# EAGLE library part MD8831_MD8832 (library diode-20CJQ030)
M-System's DiskOnChip G4 128MB (1Gb)/256MB (2Gb) 1.8V Flash Disk with MLC NAND and M-Systems x2 Technology Description: DiskOnChip G4 is M-Systems' 4th generation of the DiskOnChip family of products. Based on Multi-Level Cell (MLC) NAND, utilizing Toshiba's 90nm MLC NAND Large Block flash technology and x2 technology from MSystems, it is one of the industry's most efficient storage solutions. MLC NAND flash technology provides the smallest die size by storing 2 bits of information in a single memory cell. x2 technology enables MLC NAND to achieve highly reliable, high-performance data and code storage with a specially designed error detection and correction mechanism, optimized file management, and proprietary algorithms for enhanced performance. Further cost benefits derive from the cost-effective architecture of DiskOnChip G4, which includes a boot block that can replace expensive NOR flash, and incorporates both the flash array and an embedded thin controller in a single die. Features: Flash disk for both code and data storage Low voltage: 1.8V core and I/O Hardware protection and security-enabling features High capacity: single die - 1Gb (128MB), dual die - 2Gb (256MB) Device cascade capacity: up to 4Gb (512MB) Enhanced Programmable Boot Block enabling eXecute In Place (XIP) functionality using 16-bit interface Small form factors: 69-ball FBGA 9x12 mm package Enhanced performance by implementation of: DMA support MultiBurst operation Unrivaled data integrity with a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
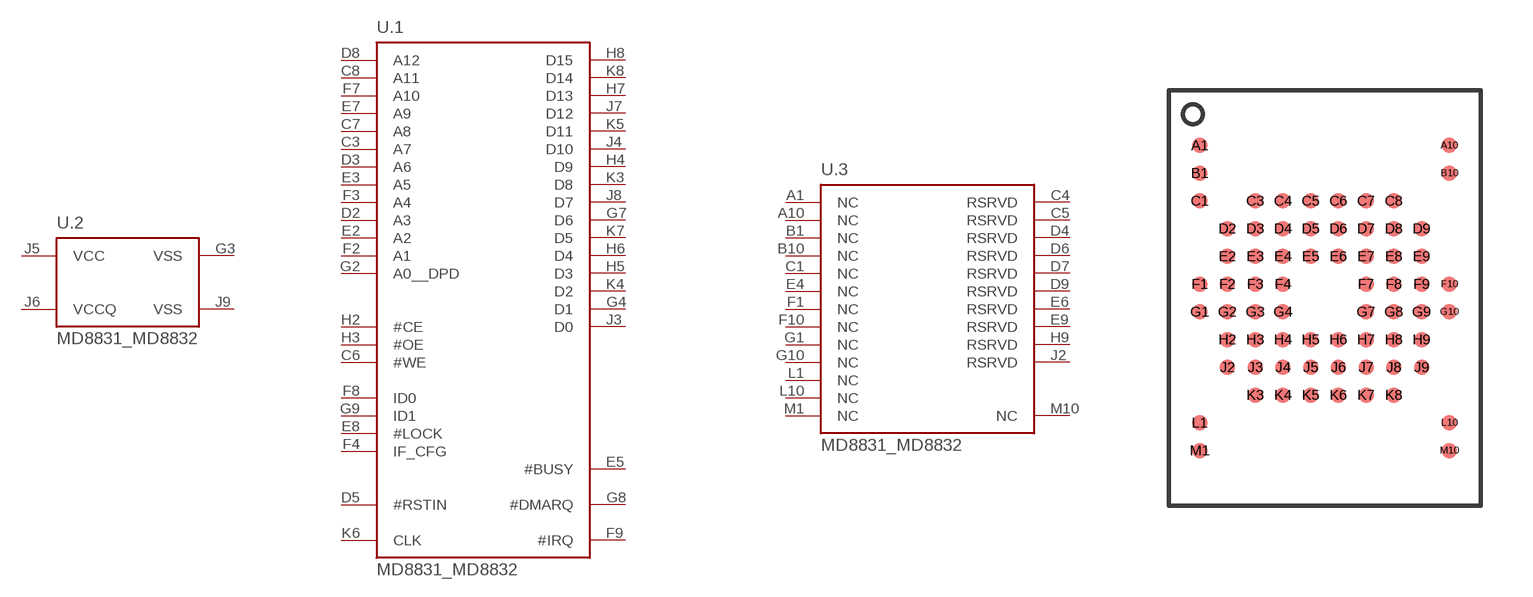
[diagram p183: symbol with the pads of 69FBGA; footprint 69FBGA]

Designator prefix U; gates .1=MD8831_MD8832 .2=MD8831_MD8832_PWR .3=MD8831_MD8832_NC

## MD8831_MD8832-D**G-V**-X-P  [69FBGA]
A1  .3:NC  nc
A10  .3:NC  nc
B1  .3:NC  nc
B10  .3:NC  nc
C1  .3:NC  nc
C3  .1:A7  in
C4  .3:RSRVD  nc
C5  .3:RSRVD  nc
C6  .1:#WE  in
C7  .1:A8  in
C8  .1:A11  in
D2  .1:A3  in
D3  .1:A6  in
D4  .3:RSRVD  nc
D5  .1:#RSTIN  in
D6  .3:RSRVD  nc
D7  .3:RSRVD  nc
D8  .1:A12  in
D9  .3:RSRVD  nc
E2  .1:A2  in
E3  .1:A5  in
E4  .3:NC  nc
E5  .1:#BUSY  out
E6  .3:RSRVD  nc
E7  .1:A9  in
E8  .1:#LOCK  in
E9  .3:RSRVD  nc
F1  .3:NC  nc
F2  .1:A1  in
F3  .1:A4  in
F4  .1:IF_CFG  in
F7  .1:A10  in
F8  .1:ID0  in
F9  .1:#IRQ  out
F10  .3:NC  nc
G1  .3:NC  nc
G2  .1:A0__DPD  in
G3  .2:VSS  pwr
G4  .1:D1
G7  .1:D6
G8  .1:#DMARQ  out
G9  .1:ID1  in
G10  .3:NC  nc
H2  .1:#CE  in
H3  .1:#OE  in
H4  .1:D9
H5  .1:D3
H6  .1:D4
H7  .1:D13
H8  .1:D15
H9  .3:RSRVD  nc
J2  .3:RSRVD  nc
J3  .1:D0
J4  .1:D10
J5  .2:VCC  pwr
J6  .2:VCCQ  pwr
J7  .1:D12
J8  .1:D7
J9  .2:VSS  pwr
K3  .1:D8
K4  .1:D2
K5  .1:D11
K6  .1:CLK  in
K7  .1:D5
K8  .1:D14
L1  .3:NC  nc
L10  .3:NC  nc
M1  .3:NC  nc
M10  .3:NC  nc

## Footprint 69FBGA (pad centres in mm)
69FBGA PAckage for the M-Systems mDoc G4
smd 0.45 x 0.45: A1 -3.6,4.4; A10 3.6,4.4; B1 -3.6,3.6; B10 3.6,3.6; C1 -3.6,2.8; C3 -2,2.8; C4 -1.2,2.8; C5 -0.4,2.8; C6 0.4,2.8; C7 1.2,2.8; C8 2,2.8; D2 -2.8,2; D3 -2,2; D4 -1.2,2; D5 -0.4,2; D6 0.4,2; D7 1.2,2; D8 2,2; D9 2.8,2; E2 -2.8,1.2; E3 -2,1.2; E4 -1.2,1.2; E5 -0.4,1.2; E6 0.4,1.2; E7 1.2,1.2; E8 2,1.2; E9 2.8,1.2; F1 -3.6,0.4; F2 -2.8,0.4; F3 -2,0.4; F4 -1.2,0.4; F7 1.2,0.4; F8 2,0.4; F9 2.8,0.4; F10 3.6,0.4; G1 -3.6,-0.4; G2 -2.8,-0.4; G3 -2,-0.4; G4 -1.2,-0.4; G7 1.2,-0.4; G8 2,-0.4; G9 2.8,-0.4; G10 3.6,-0.4; H2 -2.8,-1.2; H3 -2,-1.2; H4 -1.2,-1.2; H5 -0.4,-1.2; H6 0.4,-1.2; H7 1.2,-1.2; H8 2,-1.2; H9 2.8,-1.2; J2 -2.8,-2; J3 -2,-2; J4 -1.2,-2; J5 -0.4,-2; J6 0.4,-2; J7 1.2,-2; J8 2,-2; J9 2.8,-2; K3 -2,-2.8; K4 -1.2,-2.8; K5 -0.4,-2.8; K6 0.4,-2.8; K7 1.2,-2.8; K8 2,-2.8; L1 -3.6,-3.6; L10 3.6,-3.6; M1 -3.6,-4.4; M10 3.6,-4.4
